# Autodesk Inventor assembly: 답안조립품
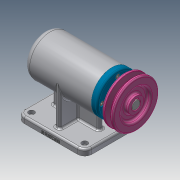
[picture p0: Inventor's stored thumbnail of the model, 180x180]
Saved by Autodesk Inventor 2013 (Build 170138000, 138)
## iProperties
Created: 2020-10
Part Number: 답안조립품
Document SubType Name: Assembly
Designer: 19
Author: 19
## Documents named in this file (12)
- C:\Users\user\Desktop\701004V1023\답안조립품.iam
- C:\Users\user\Desktop\701004V1023\본체.ipt
- C:\Users\user\Desktop\701004V1023\Ű 5 x 5 x 16.ipt
- C:\Users\user\Desktop\701004V1023\V벨트풀리.ipt
- C:\Users\user\Desktop\701004V1023\멈춤나사 M3.ipt
- C:\Users\user\Desktop\701004V1023\베어링 6004.ipt
- C:\Users\user\Desktop\701004V1023\베어링 51202.ipt
- C:\Users\user\Desktop\701004V1023\볼트 M4.ipt
- C:\Users\user\Desktop\701004V1023\어댑터슬리브.ipt
- C:\Users\user\Desktop\701004V1023\오일 실.ipt
- C:\Users\user\Desktop\701004V1023\축.ipt
- C:\Users\user\Desktop\701004V1023\커버.ipt
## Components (2 placed, 2 different names)
1. Ű 5 x 5 x 16:1
2. V벨트풀리:1 — 플러쉬:1
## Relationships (1: Flush 1)
- 플러쉬:1 [Flush]: V벨트풀리:1
